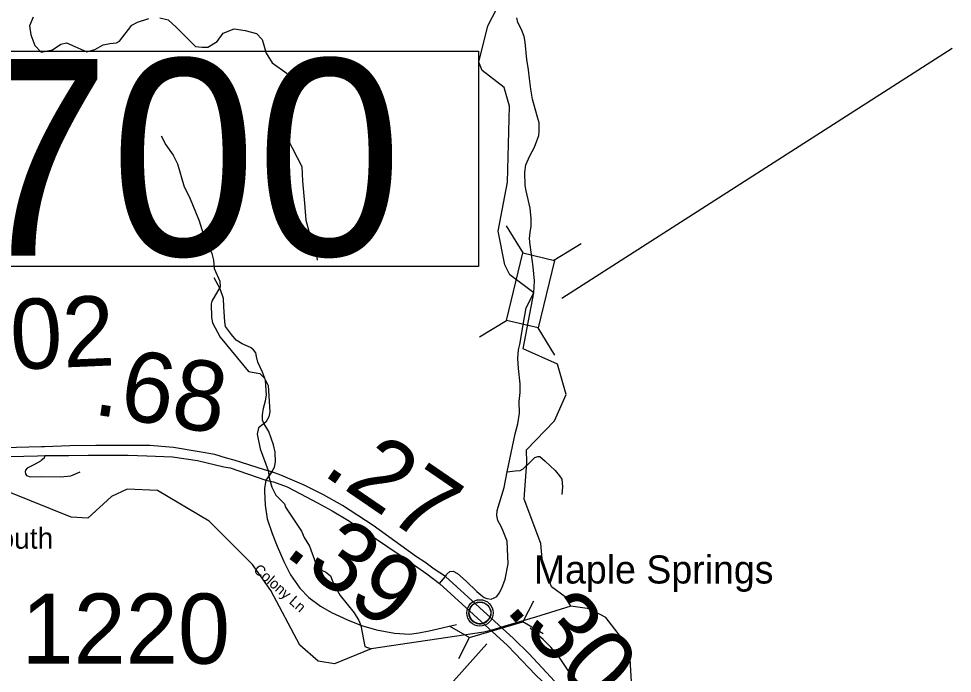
# Model space of a CAD drawing. Extents: x 1248089 to 1457196, y 820910 to 988753.
# Drawn here: x 1294020 to 1300678, y 891661 to 896327 of the extents above; entities that cross this region are included whole.
import ezdxf

# ---------------------------------------------------------------- set-up
doc = ezdxf.new("R2010")
doc.units = 0
for name, color, linetype in [('Exist Civil Demographics Community CELL', 7, 'Continuous'), ('Exist Civil Demographics Community Label', 7, 'Continuous'), ('Exist Hydrographic Creek Single Shore', 7, 'Continuous'), ('Exist Hydrographic Misc Water Feature', 7, 'Continuous'), ('Exist Road Non-System Type 51', 7, 'Continuous'), ('Exist Road Primary US Divided Attributed', 7, 'Continuous'), ('Exist Road Primary US Mileage Hundredths English Label', 7, 'Continuous'), ('Exist Road Primary US Structure Culvert CELL', 7, 'Continuous'), ('Exist Road Primary US Structure Culvert Number Label', 7, 'Continuous'), ('Exist Road Secondary Structure Standard Bridge CELL', 7, 'Continuous'), ('Exist Road Secondary Structure Standard Bridge Number Label', 7, 'Continuous'), ('Exist Road Secondary Type 51 Attributed', 7, 'Continuous'), ('Exist Road Secondary Type 51 Label', 7, 'Continuous'), ('Prop GRAU CAT1 Cell', 7, 'Continuous'), ('Prop Lane Lines', 7, 'Continuous')]:
    doc.layers.add(name, color=color, linetype=linetype)

msp = doc.modelspace()

# ---------------------------------------------------------------- linework, layer by layer
at = {"layer": 'Exist Civil Demographics Community CELL'}
msp.add_lwpolyline([(1297232, 892104), (1297233, 892109.6), (1297234.8, 892116.2), (1297237.7, 892123.4), (1297240.7, 892129.1), (1297244, 892134.9), (1297247.8, 892140), (1297251.7, 892144.4), (1297256.3, 892149), (1297261.8, 892153.5), (1297267.3, 892157.2), (1297272.1, 892160.1), (1297277.2, 892162.5), (1297282.7, 892164.8), (1297288.3, 892166.6), (1297292.6, 892167.8), (1297297.5, 892168.5), (1297301.6, 892169.3), (1297308, 892169.5), (1297312.4, 892169.4), (1297318.1, 892169.2), (1297323, 892168.4), (1297327.9, 892167.4), (1297332.9, 892166), (1297338, 892164.1), (1297344.7, 892161.2), (1297351, 892157.7), (1297356, 892154.1), (1297361.2, 892150.1), (1297364.5, 892147), (1297368.6, 892142.6), (1297372.5, 892137.9), (1297375.6, 892133.3), (1297378.7, 892128.3), (1297381.1, 892123.1), (1297383.2, 892118.1), (1297384.7, 892113.1), (1297386, 892108.5), (1297387.1, 892102.5), (1297387.7, 892097.8), (1297388, 892091.8), (1297387.8, 892086), (1297387.3, 892080.3), (1297386.3, 892074.8), (1297384.7, 892068.7), (1297382.8, 892062.8), (1297380.5, 892057.7), (1297377.3, 892051.7), (1297374.1, 892046.4), (1297370.6, 892041.7), (1297366.4, 892037), (1297361.1, 892032), (1297356.1, 892027.9), (1297351.1, 892024.5), (1297346.7, 892022), (1297339.9, 892018.7), (1297332.8, 892016), (1297326.8, 892014.5), (1297320.2, 892013.2), (1297315.8, 892012.8), (1297311.3, 892012.5), (1297305.7, 892012.5), (1297301.4, 892012.9), (1297295.8, 892013.7), (1297289.9, 892015), (1297285.3, 892016.3), (1297280.1, 892018.1), (1297275.5, 892020.1), (1297271.6, 892022.4), (1297264.8, 892026.4), (1297259.2, 892030.7), (1297254.3, 892035.2), (1297249.9, 892040.1), (1297246.7, 892044), (1297243.7, 892048.2), (1297239.6, 892055.3), (1297237.9, 892058.8), (1297236.2, 892062.9), (1297233.6, 892071.1), (1297232, 892078.1), (1297231.4, 892083.3), (1297231, 892089.6), (1297231, 892094.3), (1297231.5, 892100.7)], close=True, dxfattribs=at)
for centre, radius in [((1297309.7, 892091.6), 94.3), ((1297309.4, 892091.9), 76.7)]:
    msp.add_circle(centre, radius, dxfattribs=at)
at = {"layer": 'Exist Hydrographic Creek Single Shore'}
for points in [[(1297693.6, 894373.1), (1297521.6, 894501.9), (1297486.7, 894572.9), (1297439.6, 894812.1), (1297506.6, 895162), (1297519.7, 895703.4), (1297481.6, 895835.5), (1297325.6, 895956.8), (1297302.6, 896016.3), (1297366.2, 896276.8), (1297433.4, 896403.5)], [(1297957.6, 892139.4), (1297917.7, 892205.8), (1297819.6, 892276.8), (1297756.7, 892452), (1297743.7, 892586.8), (1297625.9, 892902.7), (1297644.7, 893162.9), (1297640.9, 893253.5), (1297840.7, 893460.9), (1297923.6, 893649.5), (1297861.9, 893864.7), (1297618.2, 893973.1), (1297693.6, 894373.1)], [(1297957.6, 892139.4), (1297705.7, 892062.4), (1297487.9, 891997.1), (1297449.4, 891985.1), (1297412.1, 891974.2), (1297338, 891953.5), (1296534.2, 891835.4), (1296271.7, 891729.9), (1296155.6, 891748.6), (1296024.6, 891863), (1295817.6, 892251.2), (1295688.6, 892437.6), (1295379.6, 892745.8), (1295009.6, 892963.4), (1294792.6, 892974.2), (1294682.7, 892920.6), (1294512.6, 892766.5), (1294395.6, 892775.3), (1293495.1, 893135.7), (1292523.6, 893288.9), (1292434.4, 893477.4), (1292385.6, 893508.8)], [(1298196.7, 890486.2), (1298134.3, 890550.9), (1298116.4, 890664.7), (1298181.1, 890903.4), (1298266.9, 891021.1), (1298276.9, 891065.7), (1298288.1, 891105.8), (1298311.5, 891268.7), (1298394.9, 891522.9), (1298376.4, 891839.8), (1298206.7, 892059.2), (1298090.7, 892120.3), (1297957.6, 892139.4)]]:
    msp.add_lwpolyline(points, dxfattribs=at)
at = {"layer": 'Exist Hydrographic Misc Water Feature'}
msp.add_lwpolyline([(1295035.9, 895492.3), (1295068.4, 895427.6), (1295122.6, 895354.3), (1295153.1, 895292.9), (1295199.1, 895127.8), (1295237.3, 895054.9), (1295307.1, 894885.2), (1295348, 894756.4), (1295397.7, 894654.4), (1295410.5, 894606.6), (1295413.1, 894546.6), (1295454.9, 894457.1), (1295457.9, 894416.9), (1295397.3, 894314.7), (1295392.9, 894295.1), (1295394.5, 894198.2), (1295401.5, 894158.6), (1295456.9, 894056.6), (1295659.2, 893812.1), (1295740.9, 893798.1), (1295772, 893764.6), (1295798.8, 893712.4), (1295810.2, 893524.2), (1295803.3, 893488.3), (1295782.3, 893452.5), (1295729.3, 893410.2), (1295720.2, 893366), (1295741.7, 893261.3), (1295800, 893107.5), (1295806.8, 893055.6), (1295825.1, 892987.2), (1295853.7, 892930), (1295916.1, 892868.8), (1295923.6, 892844.9), (1296037.5, 892673.5), (1296056.4, 892628.8), (1296095.1, 892568.1), (1296139.9, 892443.4), (1296172.9, 892398.4), (1296208.6, 892385.3), (1296243.8, 892356.7), (1296266.4, 892295.5), (1296312.5, 892214.9), (1296411.4, 892092.3), (1296446.2, 892037.5), (1296461.3, 892001.1), (1296487.7, 891853.6), (1296534.2, 891835.4)], dxfattribs=at)
at = {"layer": 'Exist Road Non-System Type 51'}
msp.add_line((1295800.8, 893071.5), (1295826, 893098.2), dxfattribs=at)
for points in [[(1294122.6, 896336.8), (1294097.4, 896277), (1294106.9, 896210.9), (1294135.2, 896135.3), (1294179.3, 896088), (1294261.1, 896103.8), (1294320.9, 896144.7), (1294361.8, 896154.2), (1294421.5, 896129), (1294506.5, 896091.2), (1294563.2, 896106.9), (1294622.9, 896141.6), (1294670.1, 896151), (1294717.3, 896154.2), (1294739.4, 896166.8), (1294827.5, 896280.1), (1294868.4, 896302.2), (1294947.1, 896327.4)], [(1295025.7, 896333.7), (1295085.5, 896317.9), (1295142.2, 896267.5), (1295280.6, 896129), (1295327.8, 896122.7), (1295368.7, 896122.7), (1295434.8, 896163.6), (1295478.9, 896223.5), (1295557.5, 896254.9), (1295636.2, 896242.3), (1295714.9, 896220.3), (1295755.8, 896179.4), (1295784.1, 896081.7), (1295828.1, 896012.5), (1295935.1, 895936.9), (1295966.6, 895870.7), (1295976, 895810.9), (1295944.6, 895735.3), (1295922.6, 895650.3), (1295922.6, 895555.8), (1295938.3, 895470.8), (1296039, 895272.4), (1296045.3, 895168.5), (1296057.9, 895011), (1296067.3, 894891.3), (1296095.6, 894787.4), (1296139.7, 894699.2), (1296149.1, 894604.7)], [(1295847.5, 893142), (1295852.4, 893168.4), (1295848.9, 893237), (1295838.3, 893290.1), (1295803.9, 893384.3), (1295770.3, 893439.1), (1295759.7, 893466.5), (1295759.7, 893504.2), (1295766.8, 893550.5), (1295780.9, 893603.6), (1295788, 893643), (1295780.1, 893751), (1295758.9, 893807.5), (1295725.3, 893879.5), (1295716.5, 893918.9), (1295711.2, 893944.6), (1295695.3, 893966.9), (1295672.3, 893984), (1295614.1, 894009.7), (1295571.7, 894035.4), (1295538.1, 894076.5), (1295495.8, 894133.1), (1295491.3, 894165.6), (1295484.3, 894273.6), (1295480.8, 894331.8), (1295456, 894402.1), (1295413.7, 894480.9)], [(1294207.1, 893212.8), (1294201.5, 893194.1), (1294179.9, 893177.5)], [(1297504.3, 893097.6), (1297561.7, 893105.3), (1297597, 893107), (1297618.2, 893119), (1297661.5, 893159.3), (1297702.1, 893198.7), (1297721.5, 893207.3), (1297735.7, 893207.3), (1297774.5, 893173), (1297845.1, 893106.2), (1297876.9, 893068.5), (1297892.8, 893044.5), (1297898.1, 892989.7), (1297894.6, 892934.8)], [(1294179.9, 893177.5), (1294175.9, 893174.4), (1294127.3, 893146.1), (1294080.5, 893123.9), (1294068.1, 893109.3), (1294066.4, 893097.3), (1294068.1, 893082.7), (1294075.2, 893071.6), (1294102.6, 893062.2), (1294179.4, 893063.9), (1294318, 893062.2), (1294392.6, 893069.9), (1294459.7, 893098.2)], [(1295826, 893098.2), (1295845.4, 893130.7), (1295847.5, 893142)], [(1298196.2, 891295.1), (1298200.9, 891308.1), (1298200.9, 891337.2), (1298190.3, 891371.5), (1298170.9, 891404), (1298103.8, 891486.3), (1297999.6, 891609.6), (1297937.8, 891681.6), (1297871.6, 891781.8), (1297815.1, 891848.6), (1297760.4, 891903.5), (1297668.6, 891982.3)]]:
    msp.add_lwpolyline(points, dxfattribs=at)
at = {"layer": 'Exist Road Primary US Divided Attributed'}
for points in [[(1295826, 893098.2), (1295773.9, 893111.9), (1295556.7, 893180.4), (1295501.9, 893194.1), (1295418.3, 893219.8), (1295306.9, 893240.5), (1295124, 893270.7), (1294956.2, 893284.5), (1294840.7, 893284.5), (1294570.9, 893285), (1294384.6, 893283.3), (1294204.8, 893275.8), (1294182.9, 893276.4), (1293913.8, 893268), (1293673.1, 893274.9), (1293492.9, 893295.5), (1293333.4, 893325.7), (1293073.5, 893386.3), (1292971.7, 893415.1), (1292893.9, 893452.8), (1292806.1, 893489.1), (1292590.2, 893588.2), (1292412.7, 893684.1), (1292340.5, 893728.9)], [(1292325.5, 893659.7), (1292386.2, 893625), (1292461.3, 893583.1), (1292621.1, 893499.1), (1292733.2, 893452.8), (1292897.4, 893382.6), (1292995.4, 893350.9), (1293126.1, 893310.6), (1293292.5, 893261.8), (1293420.1, 893240.5), (1293629.1, 893213), (1293858.8, 893204.7), (1294155.1, 893212.1), (1294207.1, 893212.8), (1294378, 893213), (1294515.8, 893216.4), (1294801.8, 893215.5), (1294934.3, 893212.1), (1295117.2, 893204.7), (1295294.6, 893177.2), (1295482.5, 893133.3), (1295528.4, 893124.7), (1295783.4, 893038.2)], [(1297063.6, 892352.4), (1296983.4, 892402.5), (1296916.3, 892453.9), (1296858.1, 892491.6), (1296547.4, 892713.7), (1296328.8, 892858.1), (1296194, 892932.4), (1296055.1, 893001.2), (1295890.4, 893072.5), (1295826, 893098.2)], [(1295783.4, 893038.2), (1295836.6, 893026.2), (1295933.7, 892990.2), (1296029, 892940.5), (1296151.4, 892876), (1296255.9, 892819.6), (1296367.3, 892752.2), (1296482.8, 892676.6), (1296741.4, 892503.3), (1296929.6, 892370), (1297020.5, 892301.4)], [(1298178.9, 891247.3), (1298104.7, 891321.4), (1297964, 891473.2), (1297661.1, 891799.7), (1297548.7, 891909.2), (1297063.6, 892352.4)], [(1297020.5, 892301.4), (1297506, 891859.9), (1297561, 891801.9), (1297705.4, 891650.6), (1297845.7, 891517.2), (1298058.8, 891273.4), (1298150, 891173.8)]]:
    msp.add_lwpolyline(points, dxfattribs=at)
at = {"layer": 'Exist Road Primary US Structure Culvert CELL'}
for p, q in [((1297691.3, 892175.8), (1297615.5, 892027.4)), ((1297090.9, 891999.3), (1297234.9, 891915.6)), ((1297234.9, 891915.6), (1297615.5, 892027.4)), ((1297759.5, 891943.7), (1297615.5, 892027.4)), ((1297159.1, 891767.2), (1297234.9, 891915.6))]:
    msp.add_line(p, q, dxfattribs=at)
at = {"layer": 'Exist Road Primary US Structure Culvert Number Label'}
msp.add_lwpolyline([(1297358.1, 891872.2), (1296308.8, 890695.7), (1294095.6, 888226.2)], dxfattribs=at)
at = {"layer": 'Exist Road Secondary Structure Standard Bridge CELL'}
for p, q in [((1297617, 894658.5), (1297498.9, 894851.6)), ((1297837.1, 894605.4), (1298030.2, 894723.5)), ((1297306.7, 894058.7), (1297499.8, 894176.8)), ((1297843, 893929.4), (1297724.9, 894122.5))]:
    msp.add_line(p, q, dxfattribs=at)
msp.add_lwpolyline([(1297499.8, 894176.8), (1297616, 894658.7), (1297841.1, 894604.5), (1297724.9, 894122.5)], close=True, dxfattribs=at)
at = {"layer": 'Exist Road Secondary Structure Standard Bridge Number Label'}
msp.add_line((1297893, 894335.8), (1300678.2, 896117.3), dxfattribs=at)
msp.add_lwpolyline([(1293582.7, 896096.2), (1297298.6, 896096.2), (1297298.6, 894559.7), (1293582.7, 894559.7)], close=True, dxfattribs=at)
at = {"layer": 'Exist Road Secondary Type 51 Attributed'}
msp.add_line((1295826, 893098.2), (1295783.4, 893038.2), dxfattribs=at)
for points in [[(1297693.6, 894373.1), (1297698.4, 894458.5), (1297688.8, 894558.5), (1297666.8, 894714.9), (1297663.3, 894761.2), (1297668.6, 894802.3), (1297675.6, 894848.6), (1297675.6, 894903.4), (1297666.8, 894975.4), (1297638.5, 895100.4), (1297632.4, 895137.3), (1297628.8, 895233.2), (1297637.7, 895286.3), (1297665.9, 895349.7), (1297697.7, 895411.4), (1297716.2, 895456.8), (1297728.6, 895494.5), (1297732.1, 895521.9), (1297732.1, 895583.6), (1297714.5, 895641.8), (1297685.3, 895752.3), (1297673, 895824.3), (1297662.4, 895901.4), (1297655.3, 895963.1), (1297642.9, 896035), (1297631.5, 896159.2), (1297624.4, 896200.3), (1297605, 896250), (1297580.3, 896299.7), (1297573.2, 896334)], [(1297063.6, 892352.4), (1297074.4, 892368.6), (1297093.8, 892387.2), (1297118.5, 892389.2), (1297150.3, 892373.7), (1297210.3, 892318.9), (1297288, 892243.5), (1297316.3, 892221.3), (1297339.2, 892200.7), (1297358.7, 892193.9), (1297388.7, 892190.4), (1297411.6, 892199), (1297429.3, 892209.3), (1297446.9, 892233.3), (1297466.4, 892269.2), (1297488.4, 892331.8), (1297509.6, 892441.4), (1297506.1, 892547.6), (1297502.6, 892602.5), (1297476.1, 892674.4), (1297460.2, 892708.7), (1297436.4, 892750.7), (1297431.1, 892786.6), (1297432.8, 892820.9), (1297481.4, 892986.2), (1297504.3, 893097.6), (1297560, 893367.4), (1297579.4, 893439.4), (1297591.7, 893516.5), (1297588.2, 893598.7), (1297595.3, 893662.1), (1297595.3, 893725.5), (1297583.8, 893834.3), (1297580.3, 893904.6), (1297585.6, 893966.2), (1297593.6, 894004.6), (1297619, 894159.4), (1297638.3, 894265.3), (1297693.6, 894373.1)], [(1295783.4, 893038.2), (1295774.3, 892979.1), (1295772.1, 892958.7), (1295778.1, 892860.8), (1295792.9, 892762.9), (1295828.5, 892657.8), (1295864.2, 892568.5), (1295911.7, 892459.1), (1295959.2, 892364.1), (1296024.5, 892269), (1296089.8, 892202.8), (1296172.9, 892140.9), (1296250.1, 892094.8), (1296365.8, 892043), (1296463.8, 892002.7), (1296570.7, 891971), (1296701.3, 891948), (1296808.2, 891939.3), (1296873.5, 891950.9), (1296947.7, 891965.3), (1297142.9, 892009.8)], [(1297020.5, 892301.4), (1297063.6, 892352.4)]]:
    msp.add_lwpolyline(points, dxfattribs=at)

# ---------------------------------------------------------------- texts
at = {"layer": 'Exist Civil Demographics Community Label'}
msp.add_text('Maple Springs', height=200, dxfattribs=at).set_placement((1297693.4, 892301.5))
at = {"layer": 'Exist Hydrographic Creek Single Shore'}
msp.add_text('South', height=150, dxfattribs=at).set_placement((1293742.2, 892549.5))
at = {"layer": 'Exist Road Primary US Mileage Hundredths English Label'}
for s, rotation, p in [('.68', 351.17797, (1294541.3, 893508.5)), ('.27', 325.62303, (1296174.9, 893085.1)), ('.30', 311.58694, (1297482, 892115.3))]:
    msp.add_text(s, height=500, rotation=rotation, dxfattribs=at).set_placement(p)
at = {"layer": 'Exist Road Secondary Structure Standard Bridge Number Label'}
msp.add_text('700', height=1400, dxfattribs=at).set_placement((1293632.9, 894638.8))
at = {"layer": 'Exist Road Secondary Type 51 Label'}
msp.add_text('Colony Ln', height=75, rotation=318.4018, dxfattribs=at).set_placement((1295688.9, 892390.8))
at = {"layer": 'Prop GRAU CAT1 Cell'}
for s, rotation, p in [('.02', 2.47651, (1293784.2, 893816.7)), ('.39', 323.32136, (1295902.7, 892511.9))]:
    msp.add_text(s, height=500, rotation=rotation, dxfattribs=at).set_placement(p)
at = {"layer": 'Prop Lane Lines'}
msp.add_text('1220', height=500, dxfattribs=at).set_placement((1294040, 891729.9))

doc.saveas('drawing.dxf')
